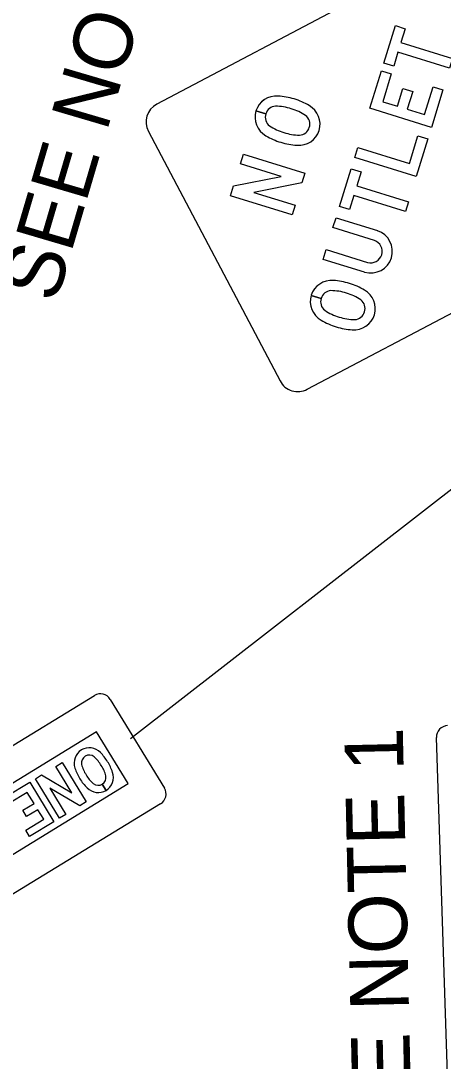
# Model space of a CAD drawing. Extents: x 2096670 to 2098561, y 684033 to 689893.
# Drawn here: x 2097638.9 to 2097725.3, y 689106 to 689318.8 of the extents above; entities that cross this region are included whole.
import ezdxf

# ---------------------------------------------------------------- set-up
doc = ezdxf.new("R2010")
doc.units = 0
for name, color, linetype in [('Prop DSN Text', 7, 'Continuous'), ('Prop Sign E No Outlet CELL', 7, 'Continuous'), ('Prop Sign E One Way_Right CELL', 7, 'Continuous')]:
    doc.layers.add(name, color=color, linetype=linetype)

msp = doc.modelspace()

# ---------------------------------------------------------------- linework, layer by layer
at = {"layer": 'Prop Sign E No Outlet CELL'}
for p, q in [((2097717.79, 689328.64), (2097666.76, 689301.71)), ((2097689.06, 689299.72), (2097687.04, 689300.35)), ((2097687.04, 689300.35), (2097689.06, 689299.72)), ((2097689.06, 689299.72), (2097687.04, 689300.35)), ((2097687.04, 689300.35), (2097689.06, 689299.72)), ((2097689.06, 689299.72), (2097689.06, 689299.72)), ((2097689.06, 689299.72), (2097689.06, 689299.72)), ((2097665.05, 689296.15), (2097691.97, 689245.12)), ((2097697.53, 689243.41), (2097748.56, 689270.33)), ((2097709.88, 689269.35), (2097709.88, 689269.35)), ((2097709.88, 689269.35), (2097709.88, 689269.35)), ((2097709.88, 689269.35), (2097709.88, 689269.35)), ((2097700.37, 689262), (2097698.34, 689262.62)), ((2097698.34, 689262.62), (2097700.37, 689262)), ((2097700.37, 689262), (2097698.34, 689262.62)), ((2097698.34, 689262.62), (2097700.37, 689262)), ((2097700.37, 689262), (2097700.37, 689262)), ((2097700.37, 689262), (2097700.37, 689262))]:
    msp.add_line(p, q, dxfattribs=at)
for points in [[(2097715.57, 689317.78), (2097717.58, 689317.16), (2097716.7, 689314.31), (2097727.27, 689311.04), (2097726.66, 689309.06), (2097716.09, 689312.33), (2097715.21, 689309.48), (2097713.2, 689310.1)], [(2097715.57, 689317.78), (2097717.58, 689317.16), (2097716.7, 689314.31), (2097727.27, 689311.04), (2097726.66, 689309.06), (2097716.09, 689312.33), (2097715.21, 689309.48), (2097713.2, 689310.1)], [(2097715.57, 689317.78), (2097717.58, 689317.16), (2097716.7, 689314.31), (2097727.27, 689311.04), (2097726.66, 689309.06), (2097716.09, 689312.33), (2097715.21, 689309.48), (2097713.2, 689310.1)], [(2097714.73, 689307.93), (2097712.97, 689302.23), (2097715.99, 689301.3), (2097717.1, 689304.9), (2097719.11, 689304.28), (2097718, 689300.68), (2097721.52, 689299.59), (2097723.29, 689305.29), (2097725.3, 689304.67), (2097722.92, 689296.98), (2097710.34, 689300.87), (2097712.72, 689308.56)], [(2097714.73, 689307.93), (2097712.97, 689302.23), (2097715.99, 689301.3), (2097717.1, 689304.9), (2097719.11, 689304.28), (2097718, 689300.68), (2097721.52, 689299.59), (2097723.29, 689305.29), (2097725.3, 689304.67), (2097722.92, 689296.98), (2097710.34, 689300.87), (2097712.72, 689308.56)], [(2097714.73, 689307.93), (2097712.97, 689302.23), (2097715.99, 689301.3), (2097717.1, 689304.9), (2097719.11, 689304.28), (2097718, 689300.68), (2097721.52, 689299.59), (2097723.29, 689305.29), (2097725.3, 689304.67), (2097722.92, 689296.98), (2097710.34, 689300.87), (2097712.72, 689308.56)], [(2097718.42, 689289.56), (2097720.18, 689295.26), (2097722.2, 689294.64), (2097719.82, 689286.95), (2097707.24, 689290.84), (2097707.86, 689292.83)], [(2097718.42, 689289.56), (2097720.18, 689295.26), (2097722.2, 689294.64), (2097719.82, 689286.95), (2097707.24, 689290.84), (2097707.86, 689292.83)], [(2097718.42, 689289.56), (2097720.18, 689295.26), (2097722.2, 689294.64), (2097719.82, 689286.95), (2097707.24, 689290.84), (2097707.86, 689292.83)], [(2097694.42, 689279.09), (2097681.84, 689282.98), (2097682.46, 689284.99), (2097692.23, 689286.9), (2097683.85, 689289.49), (2097684.46, 689291.47), (2097697.04, 689287.58), (2097696.43, 689285.6), (2097686.61, 689283.68), (2097695.03, 689281.08)], [(2097694.42, 689279.09), (2097681.84, 689282.98), (2097682.46, 689284.99), (2097692.23, 689286.9), (2097683.85, 689289.49), (2097684.46, 689291.47), (2097697.04, 689287.58), (2097696.43, 689285.6), (2097686.61, 689283.68), (2097695.03, 689281.08)], [(2097694.42, 689279.09), (2097681.84, 689282.98), (2097682.46, 689284.99), (2097692.23, 689286.9), (2097683.85, 689289.49), (2097684.46, 689291.47), (2097697.04, 689287.58), (2097696.43, 689285.6), (2097686.61, 689283.68), (2097695.03, 689281.08)], [(2097706.52, 689288.49), (2097708.53, 689287.87), (2097707.65, 689285.03), (2097718.22, 689281.76), (2097717.6, 689279.78), (2097707.03, 689283.05), (2097706.15, 689280.19), (2097704.14, 689280.81)], [(2097706.52, 689288.49), (2097708.53, 689287.87), (2097707.65, 689285.03), (2097718.22, 689281.76), (2097717.6, 689279.78), (2097707.03, 689283.05), (2097706.15, 689280.19), (2097704.14, 689280.81)], [(2097706.52, 689288.49), (2097708.53, 689287.87), (2097707.65, 689285.03), (2097718.22, 689281.76), (2097717.6, 689279.78), (2097707.03, 689283.05), (2097706.15, 689280.19), (2097704.14, 689280.81)]]:
    msp.add_lwpolyline(points, close=True, dxfattribs=at)
for points in [[(2097711.28, 689273.87), (2097702.8, 689276.49), (2097703.42, 689278.47), (2097711.89, 689275.85)], [(2097711.28, 689273.87), (2097702.8, 689276.49), (2097703.42, 689278.47), (2097711.89, 689275.85)], [(2097711.28, 689273.87), (2097702.8, 689276.49), (2097703.42, 689278.47), (2097711.89, 689275.85)], [(2097709.26, 689267.36), (2097700.79, 689269.98), (2097701.4, 689271.97), (2097709.88, 689269.35)], [(2097709.26, 689267.36), (2097700.79, 689269.98), (2097701.4, 689271.97), (2097709.88, 689269.35)], [(2097709.26, 689267.36), (2097700.79, 689269.98), (2097701.4, 689271.97), (2097709.88, 689269.35)]]:
    msp.add_lwpolyline(points, dxfattribs=at)
for centre, start, end in [((2097668.68, 689298.07), 117.8167, 207.8167), ((2097695.61, 689247.04), 207.8167, 297.8167)]:
    msp.add_arc(centre, 4.12, start, end, dxfattribs=at)
for centre, major_axis, start_param, end_param in [((2097691.29, 689299), (-4.26, 1.32), 4.940915, 6.276178), ((2097691.29, 689299), (-4.26, 1.32), 4.940915, 6.27603), ((2097691.29, 689299), (-4.26, 1.32), 4.940915, 6.27603), ((2097690.88, 689290.08), (-12.91, 3.99), 4.707364, 4.955713), ((2097690.88, 689290.08), (-12.91, 3.99), 4.707364, 4.955713), ((2097690.88, 689290.08), (-12.91, 3.99), 4.707364, 4.955713), ((2097691.01, 689290.04), (-12.91, 3.99), 4.469065, 4.717414), ((2097691.01, 689290.04), (-12.91, 3.99), 4.469065, 4.717414), ((2097691.01, 689290.04), (-12.91, 3.99), 4.469065, 4.717414), ((2097691.3, 689299.06), (-4.26, 1.32), 0.007008, 1.34227), ((2097691.3, 689299.06), (-4.26, 1.32), 0.007008, 1.34227), ((2097691.3, 689299.06), (-4.26, 1.32), 0.007008, 1.34227), ((2097691.18, 689299.13), (-2.1, 0.65), 5.062003, 6.314032), ((2097691.18, 689299.13), (-2.1, 0.65), 5.062003, 6.313732), ((2097691.18, 689299.13), (-2.1, 0.65), 5.062003, 6.313732), ((2097691.15, 689291.52), (-9.47, 2.93), 4.688261, 5.016143), ((2097691.15, 689291.52), (-9.47, 2.93), 4.688261, 5.016143), ((2097691.15, 689291.52), (-9.47, 2.93), 4.688261, 5.016143), ((2097691.6, 689291.38), (-9.47, 2.93), 4.408635, 4.736517), ((2097691.6, 689291.38), (-9.47, 2.93), 4.408635, 4.736517), ((2097691.6, 689291.38), (-9.47, 2.93), 4.408635, 4.736517), ((2097695.71, 689297.63), (-4.26, 1.32), 3.1486, 4.483863), ((2097695.71, 689297.63), (-4.26, 1.32), 3.1486, 4.483863), ((2097695.71, 689297.63), (-4.26, 1.32), 3.1486, 4.483863), ((2097691.14, 689299), (-2.1, 0.65), 6.252339, 7.504367), ((2097691.14, 689299), (-2.1, 0.65), 6.252339, 7.504367), ((2097691.14, 689299), (-2.1, 0.65), 6.252339, 7.504367), ((2097695.87, 689297.68), (-2.1, 0.65), 3.110746, 4.362774), ((2097695.87, 689297.68), (-2.1, 0.65), 3.110746, 4.362775), ((2097695.87, 689297.68), (-2.1, 0.65), 3.110746, 4.362775), ((2097695.41, 689305.31), (-9.47, 2.93), 1.267043, 1.594924), ((2097695.41, 689305.31), (-9.47, 2.93), 1.267042, 1.594924), ((2097695.41, 689305.31), (-9.47, 2.93), 1.267042, 1.594924), ((2097695.87, 689305.17), (-9.47, 2.93), 1.546668, 1.87455), ((2097695.87, 689305.17), (-9.47, 2.93), 1.546668, 1.87455), ((2097695.87, 689305.17), (-9.47, 2.93), 1.546668, 1.87455), ((2097695.73, 689297.69), (-4.26, 1.32), 1.799323, 3.134585), ((2097695.73, 689297.69), (-4.26, 1.32), 1.799323, 3.134585), ((2097695.73, 689297.69), (-4.26, 1.32), 1.799323, 3.134585), ((2097695.83, 689297.56), (-2.1, 0.65), 1.920411, 3.172439), ((2097695.83, 689297.56), (-2.1, 0.65), 1.920411, 3.172439), ((2097695.83, 689297.56), (-2.1, 0.65), 1.920411, 3.172439), ((2097696, 689306.65), (-12.91, 3.99), 1.327472, 1.575821), ((2097696, 689306.65), (-12.91, 3.99), 1.327472, 1.575821), ((2097696, 689306.65), (-12.91, 3.99), 1.327472, 1.575821), ((2097696.13, 689306.61), (-12.91, 3.99), 1.565772, 1.814121), ((2097696.13, 689306.61), (-12.91, 3.99), 1.565772, 1.814121), ((2097696.13, 689306.61), (-12.91, 3.99), 1.565772, 1.814121), ((2097710.45, 689271.64), (-4.31, 1.33), 1.600774, 4.682411), ((2097710.45, 689271.64), (-4.31, 1.33), 1.600774, 4.682411), ((2097710.45, 689271.64), (-4.31, 1.33), 1.600774, 4.682411), ((2097710.46, 689271.64), (-2.3, 0.71), 1.62358, 4.659605), ((2097710.46, 689271.64), (-2.3, 0.71), 1.62358, 4.659605), ((2097710.46, 689271.64), (-2.3, 0.71), 1.62358, 4.659605), ((2097702.59, 689261.28), (-4.26, 1.32), 4.940915, 6.276178), ((2097702.59, 689261.28), (-4.26, 1.32), 4.940915, 6.27603), ((2097702.59, 689261.28), (-4.26, 1.32), 4.940915, 6.27603), ((2097702.18, 689252.35), (-12.91, 3.99), 4.707364, 4.955713), ((2097702.18, 689252.35), (-12.91, 3.99), 4.707364, 4.955713), ((2097702.18, 689252.35), (-12.91, 3.99), 4.707364, 4.955713), ((2097702.31, 689252.31), (-12.91, 3.99), 4.469065, 4.717414), ((2097702.31, 689252.31), (-12.91, 3.99), 4.469065, 4.717414), ((2097702.31, 689252.31), (-12.91, 3.99), 4.469065, 4.717414), ((2097702.61, 689261.33), (-4.26, 1.32), 0.007008, 1.34227), ((2097702.61, 689261.33), (-4.26, 1.32), 0.007008, 1.34227), ((2097702.61, 689261.33), (-4.26, 1.32), 0.007008, 1.34227), ((2097702.45, 689261.28), (-2.1, 0.65), 6.252339, 7.504367), ((2097702.45, 689261.28), (-2.1, 0.65), 6.252339, 7.504367), ((2097702.45, 689261.28), (-2.1, 0.65), 6.252339, 7.504367), ((2097702.49, 689261.41), (-2.1, 0.65), 5.062003, 6.314032), ((2097702.49, 689261.41), (-2.1, 0.65), 5.062003, 6.313732), ((2097702.49, 689261.41), (-2.1, 0.65), 5.062003, 6.313732), ((2097702.45, 689253.8), (-9.47, 2.93), 4.688261, 5.016143), ((2097702.45, 689253.8), (-9.47, 2.93), 4.688261, 5.016143), ((2097702.45, 689253.8), (-9.47, 2.93), 4.688261, 5.016143), ((2097702.91, 689253.66), (-9.47, 2.93), 4.408635, 4.736517), ((2097702.91, 689253.66), (-9.47, 2.93), 4.408635, 4.736517), ((2097702.91, 689253.66), (-9.47, 2.93), 4.408635, 4.736517), ((2097707.01, 689259.91), (-4.26, 1.32), 3.1486, 4.483863), ((2097707.01, 689259.91), (-4.26, 1.32), 3.1486, 4.483863), ((2097707.01, 689259.91), (-4.26, 1.32), 3.1486, 4.483863), ((2097707.17, 689259.96), (-2.1, 0.65), 3.110746, 4.362774), ((2097707.17, 689259.96), (-2.1, 0.65), 3.110746, 4.362775), ((2097707.17, 689259.96), (-2.1, 0.65), 3.110746, 4.362775), ((2097707.31, 689268.93), (-12.91, 3.99), 1.327472, 1.575821), ((2097707.31, 689268.93), (-12.91, 3.99), 1.327472, 1.575821), ((2097707.31, 689268.93), (-12.91, 3.99), 1.327472, 1.575821), ((2097706.72, 689267.58), (-9.47, 2.93), 1.267043, 1.594924), ((2097706.72, 689267.58), (-9.47, 2.93), 1.267042, 1.594924), ((2097706.72, 689267.58), (-9.47, 2.93), 1.267042, 1.594924), ((2097707.17, 689267.44), (-9.47, 2.93), 1.546668, 1.87455), ((2097707.17, 689267.44), (-9.47, 2.93), 1.546668, 1.87455), ((2097707.17, 689267.44), (-9.47, 2.93), 1.546668, 1.87455), ((2097707.03, 689259.97), (-4.26, 1.32), 1.799323, 3.134585), ((2097707.03, 689259.97), (-4.26, 1.32), 1.799323, 3.134585), ((2097707.03, 689259.97), (-4.26, 1.32), 1.799323, 3.134585), ((2097707.13, 689259.83), (-2.1, 0.65), 1.920411, 3.172439), ((2097707.13, 689259.83), (-2.1, 0.65), 1.920411, 3.172439), ((2097707.13, 689259.83), (-2.1, 0.65), 1.920411, 3.172439), ((2097707.44, 689268.89), (-12.91, 3.99), 1.565772, 1.814121), ((2097707.44, 689268.89), (-12.91, 3.99), 1.565772, 1.814121), ((2097707.44, 689268.89), (-12.91, 3.99), 1.565772, 1.814121)]:
    msp.add_ellipse(centre, major_axis=major_axis, ratio=0.985, start_param=start_param, end_param=end_param, dxfattribs=at)
at = {"layer": 'Prop Sign E One Way_Right CELL'}
for p, q in [((2097661.38, 689171.97), (2097881.91, 689343.44)), ((2097587.43, 689140.19), (2097653.99, 689180.78)), ((2097657.23, 689179.99), (2097668.3, 689161.84)), ((2097726.5, 689094.25), (2097723.97, 689172.17)), ((2097655.59, 689162.65), (2097656.38, 689161.36)), ((2097656.38, 689161.36), (2097655.59, 689162.65)), ((2097655.59, 689162.65), (2097655.59, 689162.65)), ((2097655.59, 689162.65), (2097656.38, 689161.36)), ((2097656.38, 689161.36), (2097655.59, 689162.65)), ((2097655.59, 689162.65), (2097655.59, 689162.65)), ((2097667.52, 689158.59), (2097600.96, 689118))]:
    msp.add_line(p, q, dxfattribs=at)
msp.add_lwpolyline([(2097616.69, 689131.68), (2097614.09, 689134.06), (2097660.89, 689162.81), (2097654.4, 689173.38), (2097607.6, 689144.63), (2097606.65, 689148.03)], dxfattribs=at)
for points in [[(2097647.38, 689167.07), (2097652.3, 689159), (2097651.01, 689158.22), (2097644.85, 689161.82), (2097648.12, 689156.45), (2097646.85, 689155.68), (2097641.93, 689163.75), (2097643.2, 689164.52), (2097649.4, 689160.89), (2097646.1, 689166.29)], [(2097647.38, 689167.07), (2097652.3, 689159), (2097651.01, 689158.22), (2097644.85, 689161.82), (2097648.12, 689156.45), (2097646.85, 689155.68), (2097641.93, 689163.75), (2097643.2, 689164.52), (2097649.4, 689160.89), (2097646.1, 689166.29)], [(2097647.38, 689167.07), (2097652.3, 689159), (2097651.01, 689158.22), (2097644.85, 689161.82), (2097648.12, 689156.45), (2097646.85, 689155.68), (2097641.93, 689163.75), (2097643.2, 689164.52), (2097649.4, 689160.89), (2097646.1, 689166.29)], [(2097639.96, 689153.25), (2097643.62, 689155.48), (2097642.44, 689157.41), (2097640.13, 689156.01), (2097639.34, 689157.3), (2097641.65, 689158.71), (2097640.27, 689160.96), (2097636.62, 689158.74), (2097635.83, 689160.03), (2097640.76, 689163.03), (2097645.68, 689154.96), (2097640.75, 689151.96)], [(2097639.96, 689153.25), (2097643.62, 689155.48), (2097642.44, 689157.41), (2097640.13, 689156.01), (2097639.34, 689157.3), (2097641.65, 689158.71), (2097640.27, 689160.96), (2097636.62, 689158.74), (2097635.83, 689160.03), (2097640.76, 689163.03), (2097645.68, 689154.96), (2097640.75, 689151.96)], [(2097639.96, 689153.25), (2097643.62, 689155.48), (2097642.44, 689157.41), (2097640.13, 689156.01), (2097639.34, 689157.3), (2097641.65, 689158.71), (2097640.27, 689160.96), (2097636.62, 689158.74), (2097635.83, 689160.03), (2097640.76, 689163.03), (2097645.68, 689154.96), (2097640.75, 689151.96)]]:
    msp.add_lwpolyline(points, close=True, dxfattribs=at)
for centre, start, end in [((2097655.22, 689178.76), 31.3775, 121.3766), ((2097726.33, 689172.25), 91.8571, 181.8562), ((2097666.29, 689160.61), 301.3766, 31.3775)]:
    msp.add_arc(centre, 2.36, start, end, dxfattribs=at)
for centre, major_axis, start_param, end_param in [((2097652.97, 689166.91), (1.67, -2.73), 1.799323, 3.134585), ((2097652.97, 689166.91), (1.67, -2.73), 1.799323, 3.134585), ((2097652.97, 689166.91), (1.67, -2.73), 1.799323, 3.134585), ((2097653.01, 689166.93), (1.67, -2.73), 3.1486, 4.483863), ((2097653.01, 689166.93), (1.67, -2.73), 3.1486, 4.483863), ((2097653.01, 689166.93), (1.67, -2.73), 3.1486, 4.483863), ((2097652.9, 689166.98), (0.82, -1.35), 3.110746, 4.362774), ((2097652.9, 689166.98), (0.82, -1.35), 3.110746, 4.362775), ((2097652.9, 689166.98), (0.82, -1.35), 3.110746, 4.362775), ((2097652.98, 689167.03), (0.82, -1.35), 1.920411, 3.172439), ((2097652.98, 689167.03), (0.82, -1.35), 1.920411, 3.172439), ((2097652.98, 689167.03), (0.82, -1.35), 1.920411, 3.172439), ((2097649.34, 689162.95), (3.7, -6.07), 1.546668, 1.87455), ((2097649.34, 689162.95), (3.7, -6.07), 1.546668, 1.87455), ((2097649.34, 689162.95), (3.7, -6.07), 1.546668, 1.87455), ((2097648.51, 689162.3), (5.05, -8.28), 1.565772, 1.814121), ((2097648.51, 689162.3), (5.05, -8.28), 1.565772, 1.814121), ((2097648.51, 689162.3), (5.05, -8.28), 1.565772, 1.814121), ((2097659.14, 689168.78), (5.05, -8.28), 4.469065, 4.717414), ((2097659.14, 689168.78), (5.05, -8.28), 4.469065, 4.717414), ((2097659.14, 689168.78), (5.05, -8.28), 4.469065, 4.717414), ((2097658.18, 689168.34), (3.7, -6.07), 4.408635, 4.736517), ((2097658.18, 689168.34), (3.7, -6.07), 4.408635, 4.736517), ((2097658.18, 689168.34), (3.7, -6.07), 4.408635, 4.736517), ((2097649.52, 689162.66), (3.7, -6.07), 1.267043, 1.594924), ((2097649.52, 689162.66), (3.7, -6.07), 1.267042, 1.594924), ((2097649.52, 689162.66), (3.7, -6.07), 1.267042, 1.594924), ((2097648.56, 689162.22), (5.05, -8.28), 1.327472, 1.575821), ((2097648.56, 689162.22), (5.05, -8.28), 1.327472, 1.575821), ((2097648.56, 689162.22), (5.05, -8.28), 1.327472, 1.575821), ((2097658.36, 689168.05), (3.7, -6.07), 4.688261, 5.016143), ((2097658.36, 689168.05), (3.7, -6.07), 4.688261, 5.016143), ((2097658.36, 689168.05), (3.7, -6.07), 4.688261, 5.016143), ((2097654.81, 689164.03), (0.82, -1.35), 6.252339, 7.504367), ((2097654.81, 689164.03), (0.82, -1.35), 6.252339, 7.504367), ((2097654.81, 689164.03), (0.82, -1.35), 6.252339, 7.504367), ((2097654.7, 689164.07), (1.67, -2.73), 0.007008, 1.34227), ((2097654.7, 689164.07), (1.67, -2.73), 0.007008, 1.34227), ((2097654.7, 689164.07), (1.67, -2.73), 0.007008, 1.34227), ((2097659.19, 689168.7), (5.05, -8.28), 4.707364, 4.955713), ((2097659.19, 689168.7), (5.05, -8.28), 4.707364, 4.955713), ((2097659.19, 689168.7), (5.05, -8.28), 4.707364, 4.955713), ((2097654.74, 689164.1), (1.67, -2.73), 4.940915, 6.276178), ((2097654.74, 689164.1), (1.67, -2.73), 4.940915, 6.27603), ((2097654.74, 689164.1), (1.67, -2.73), 4.940915, 6.27603), ((2097654.73, 689163.98), (0.82, -1.35), 5.062003, 6.314032), ((2097654.73, 689163.98), (0.82, -1.35), 5.062003, 6.313732), ((2097654.73, 689163.98), (0.82, -1.35), 5.062003, 6.313732)]:
    msp.add_ellipse(centre, major_axis=major_axis, ratio=0.985, start_param=start_param, end_param=end_param, dxfattribs=at)

# ---------------------------------------------------------------- texts
at = {"layer": 'Prop DSN Text'}
for s, rotation, p in [('SEE NOTE 3', 73.5869, (2097646.16, 689260.79)), ('SEE NOTE 1', 91.2688, (2097719.16, 689079.84))]:
    msp.add_text(s, height=12, rotation=rotation, dxfattribs=at).set_placement(p)

doc.saveas('drawing.dxf')
